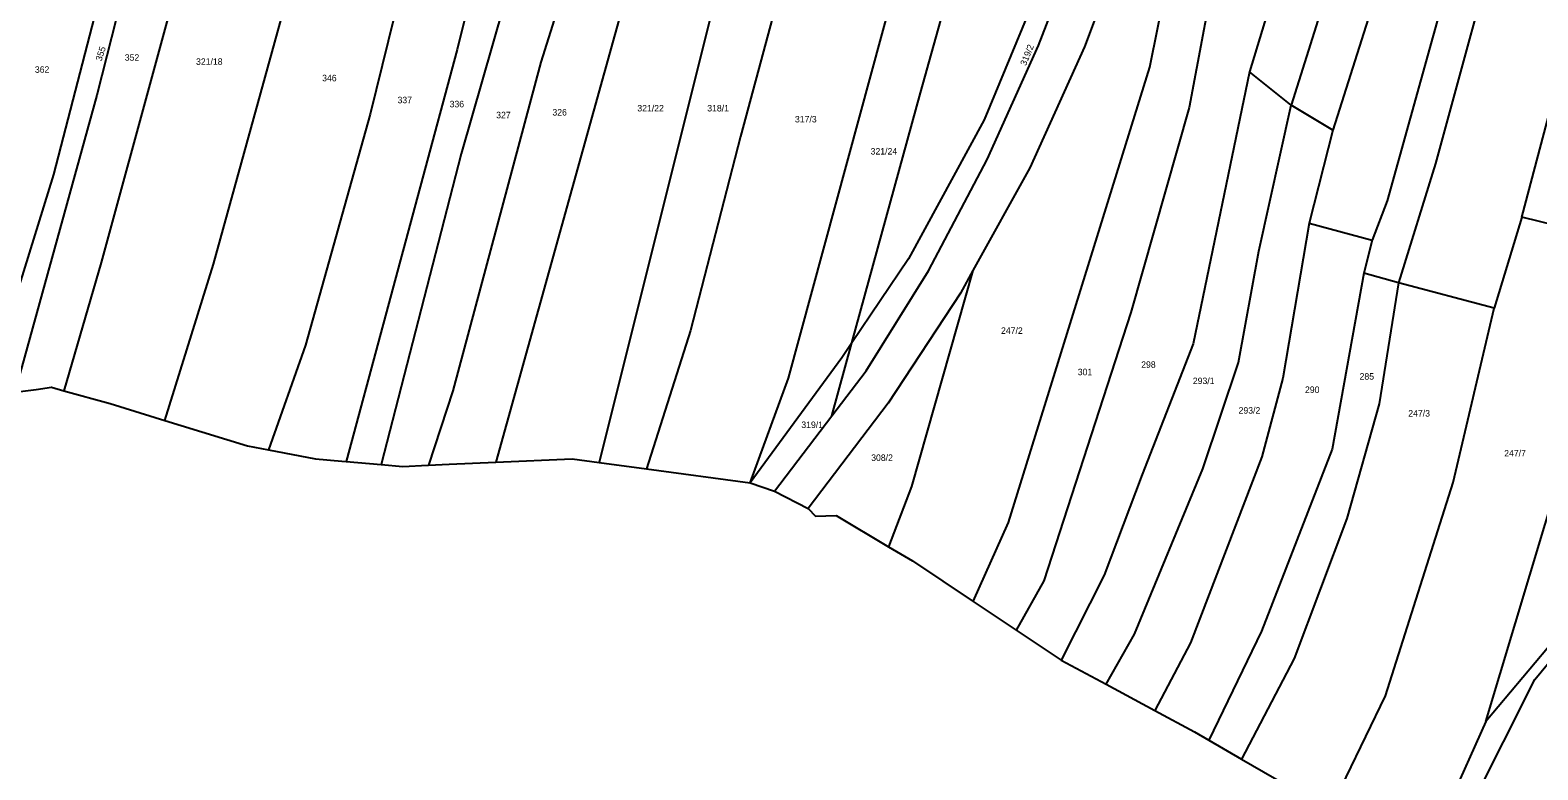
# Model space of a CAD drawing. Extents: x -744566 to -741843, y -1128407 to -1126744.
# Drawn here: x -743655.8 to -743260.5, y -1128082 to -1127888.2 of the extents above; entities that cross this region are included whole.
import ezdxf

# ---------------------------------------------------------------- set-up
doc = ezdxf.new("R2010")
doc.units = 0
doc.layers.add('Hranice parcel', color=7, linetype='Continuous')
doc.layers.add('Parcelní čísla', color=7, linetype='Continuous')

msp = doc.modelspace()

# ---------------------------------------------------------------- linework, layer by layer
at = {"layer": 'Hranice parcel'}
for p, q in [((-743490.01, -1127844.27), (-743533.73, -1128001.44)), ((-743327.83, -1127872.04), (-743336.15, -1127899.16)), ((-743325.19, -1127907.9), (-743336.15, -1127899.16)), ((-743314.24, -1127914.43), (-743325.19, -1127907.9)), ((-743314.24, -1127914.43), (-743320.49, -1127938.82)), ((-743320.49, -1127938.82), (-743303.92, -1127943.26)), ((-743264.74, -1127937.21), (-743271.96, -1127961.06)), ((-743237.87, -1127943.87), (-743264.74, -1127937.21)), ((-743303.92, -1127943.26), (-743306.09, -1127951.87)), ((-743297.04, -1127954.42), (-743306.09, -1127951.87)), ((-743271.96, -1127961.06), (-743297.04, -1127954.42)), ((-743445.65, -1127989.32), (-743440.39, -1127970.17)), ((-743659.84, -1127983.12), (-743654.23, -1127982.34)), ((-743646.98, -1127982.69), (-743634.85, -1127986.07)), ((-743634.85, -1127986.07), (-743620.48, -1127990.48)), ((-743620.48, -1127990.48), (-743616.23, -1127991.79)), ((-743460.67, -1128009.01), (-743445.65, -1127989.32)), ((-743616.23, -1127991.79), (-743598.82, -1127997.13)), ((-743598.82, -1127997.13), (-743593.27, -1127998.19)), ((-743574.12, -1128001.12), (-743572.96, -1128001.22)), ((-743572.96, -1128001.22), (-743563.76, -1128002.02)), ((-743551.55, -1128002.22), (-743551.38, -1128002.22)), ((-743551.38, -1128002.22), (-743545.92, -1128001.98)), ((-743545.92, -1128001.98), (-743533.73, -1128001.44)), ((-743506.61, -1128001.51), (-743494.24, -1128003.18)), ((-743494.24, -1128003.18), (-743467.06, -1128006.86)), ((-743467.06, -1128006.86), (-743460.67, -1128009.01)), ((-743460.67, -1128009.01), (-743451.84, -1128013.54)), ((-743444.44, -1128015.41), (-743430.75, -1128023.58)), ((-743232.97, -1128020.31), (-743274.12, -1128069.36)), ((-743430.75, -1128023.58), (-743424.49, -1128027.31)), ((-743424.49, -1128027.31), (-743408.55, -1128037.93)), ((-743408.55, -1128037.93), (-743397.3, -1128045.42)), ((-743397.3, -1128045.42), (-743385.5, -1128053.28)), ((-743385.5, -1128053.28), (-743373.72, -1128059.62)), ((-743373.72, -1128059.62), (-743360.94, -1128066.49)), ((-743274.12, -1128069.36), (-743294.54, -1128114.63)), ((-743346.77, -1128074.27), (-743338.22, -1128079.2)), ((-743338.22, -1128079.2), (-743323.15, -1128087.88))]:
    msp.add_line(p, q, dxfattribs=at)
for points in [[(-743264.74, -1127937.21), (-743244.37, -1127860.25), (-743227.42, -1127799.64), (-743205.44, -1127708.1), (-743196.8, -1127679.29)], [(-743225.59, -1127692.63), (-743249.75, -1127785.46), (-743287.33, -1127923.2), (-743297.04, -1127954.42)], [(-743235.82, -1127698.28), (-743249, -1127749.54), (-743300.05, -1127932.95), (-743303.92, -1127943.26)], [(-743253.81, -1127707.15), (-743266.62, -1127751.47), (-743299.27, -1127867.01), (-743314.24, -1127914.43)], [(-743268.66, -1127713.55), (-743299.42, -1127819.01), (-743313.64, -1127871.22), (-743325.19, -1127907.9)], [(-743603.54, -1127766.74), (-743612.96, -1127791.11), (-743627.05, -1127838.6), (-743649.69, -1127926.04), (-743667.73, -1127984.22)], [(-743597.33, -1127768.16), (-743606.36, -1127789.97), (-743626.72, -1127859.49), (-743638.35, -1127905.26), (-743659.84, -1127983.12)], [(-743587.1, -1127780.87), (-743593.35, -1127794.42), (-743608.73, -1127844.98), (-743637.18, -1127949.14), (-743646.98, -1127982.69)], [(-743440.39, -1127970.17), (-743422.4, -1127904.63), (-743393.77, -1127802.48), (-743383.94, -1127781.89)], [(-743451.09, -1127794.94), (-743476.79, -1127882.29), (-743506.61, -1128001.51)], [(-743376.61, -1127794.9), (-743373.1, -1127812.6), (-743383.25, -1127857.46), (-743405.64, -1127911.7), (-743425.47, -1127948.11), (-743440.39, -1127970.17)], [(-743521.42, -1127813.7), (-743536.99, -1127865.85), (-743543.84, -1127893.3), (-743572.96, -1128001.22)], [(-743355.31, -1127817.79), (-743356.91, -1127824.97), (-743366.89, -1127859.22), (-743379.33, -1127892.58), (-743393.74, -1127924.28), (-743408.65, -1127951.21)], [(-743444.74, -1127823.92), (-743469.54, -1127916.07), (-743482.7, -1127966.88), (-743494.24, -1128003.18)], [(-743620.48, -1127990.48), (-743607.74, -1127949.5), (-743573.69, -1127826.51)], [(-743513.93, -1127828.42), (-743520.57, -1127843.27), (-743542.77, -1127920.67), (-743563.76, -1128002.02)], [(-743467.06, -1128006.86), (-743456.95, -1127979.38), (-743416.75, -1127831.61)], [(-743549.4, -1127840.4), (-743566.66, -1127910.22), (-743583.63, -1127970.8), (-743593.27, -1127998.19)], [(-743504.76, -1127842.24), (-743521.89, -1127896.66), (-743544.94, -1127982.71), (-743551.38, -1128002.22)], [(-743408.55, -1128037.93), (-743399.31, -1128017.21), (-743362.28, -1127897.95), (-743351.87, -1127846.33)], [(-743344, -1127866.17), (-743351.96, -1127908.52), (-743367.18, -1127962.23), (-743390, -1128032.51), (-743397.3, -1128045.42)], [(-743445.65, -1127989.32), (-743436.62, -1127977.47), (-743420.24, -1127951.33), (-743404.89, -1127922.15), (-743391.42, -1127892.28), (-743388.31, -1127884.17)], [(-743336.15, -1127899.16), (-743350.84, -1127970.39), (-743364.27, -1128004.65), (-743374.19, -1128031.01), (-743385.5, -1128053.28)], [(-743373.72, -1128059.62), (-743366.24, -1128046.5), (-743348.37, -1128003.17), (-743339.02, -1127975.31), (-743333.67, -1127946.14), (-743325.19, -1127907.9)], [(-743320.49, -1127938.82), (-743327.4, -1127979.41), (-743332.84, -1128000.03), (-743351.58, -1128048.72), (-743360.94, -1128066.49)], [(-743274.12, -1128069.36), (-743254.82, -1128005.17), (-743237.87, -1127943.87)], [(-743408.65, -1127951.21), (-743411.91, -1127957.1), (-743430.86, -1127985.98), (-743451.84, -1128013.54)], [(-743408.65, -1127951.21), (-743424.74, -1128007.83), (-743430.75, -1128023.58)], [(-743306.09, -1127951.87), (-743314.44, -1127998.01), (-743332.92, -1128045.71), (-743346.77, -1128074.27)], [(-743297.04, -1127954.42), (-743302.13, -1127986.13), (-743310.6, -1128016.21), (-743324.39, -1128052.82), (-743338.22, -1128079.2)], [(-743315.96, -1128094.6), (-743300.41, -1128062.62), (-743282.67, -1128006.78), (-743271.96, -1127961.06)], [(-743440.39, -1127970.17), (-743443.01, -1127974.04), (-743467.06, -1128006.86)], [(-743654.23, -1127982.34), (-743650.24, -1127981.78), (-743646.98, -1127982.69)], [(-743593.27, -1127998.19), (-743581.01, -1128000.52), (-743574.12, -1128001.12)], [(-743563.76, -1128002.02), (-743558.09, -1128002.51), (-743551.55, -1128002.22)], [(-743533.73, -1128001.44), (-743513.65, -1128000.56), (-743506.61, -1128001.51)], [(-743451.84, -1128013.54), (-743449.85, -1128015.59), (-743444.44, -1128015.41)], [(-743286.03, -1128107.53), (-743261.3, -1128058.36), (-743228.15, -1128018.27)], [(-743360.94, -1128066.49), (-743350.56, -1128072.08), (-743346.77, -1128074.27)]]:
    msp.add_lwpolyline(points, dxfattribs=at)

# ---------------------------------------------------------------- texts
at = {"layer": 'Parcelní čísla'}
for s, rotation, p in [('319/2', 68, (-743394.721, -1127897.688)), ('355', 72, (-743637.081, -1127896.462))]:
    msp.add_text(s, height=1.7, rotation=rotation, dxfattribs=at).set_placement(p)
for s, p in [('352', (-743630.98, -1127896.24)), ('321/18', (-743612.3, -1127897.32)), ('362', (-743654.55, -1127899.4)), ('346', (-743579.24, -1127901.63)), ('337', (-743559.48, -1127907.38)), ('336', (-743545.82, -1127908.45)), ('321/22', (-743496.6, -1127909.53)), ('318/1', (-743478.27, -1127909.53)), ('327', (-743533.61, -1127911.33)), ('326', (-743518.87, -1127910.61)), ('317/3', (-743455.28, -1127912.41)), ('321/24', (-743435.44, -1127920.82)), ('247/2', (-743401.25, -1127967.8)), ('298', (-743364.5, -1127976.7)), ('301', (-743381.13, -1127978.64)), ('285', (-743307.25, -1127979.8)), ('293/1', (-743350.96, -1127980.96)), ('290', (-743321.56, -1127983.28)), ('319/1', (-743453.61, -1127992.47)), ('293/2', (-743338.97, -1127988.7)), ('247/3', (-743294.48, -1127989.47)), ('247/7', (-743269.33, -1127999.93)), ('308/2', (-743435.29, -1128001.09))]:
    msp.add_text(s, height=1.7, dxfattribs=at).set_placement(p)

doc.saveas('drawing.dxf')
